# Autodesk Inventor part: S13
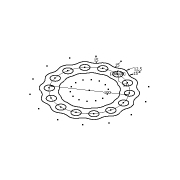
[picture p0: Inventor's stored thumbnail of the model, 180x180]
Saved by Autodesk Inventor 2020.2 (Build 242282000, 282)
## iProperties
Created: 2016-06
Part Number: S13
Material: Ogólny
Document SubType Name: Modeling
Designer: F.Stasiak
Density: 1 g/cm^3
Appearance: Domyślna
Manager: www.cadconsulting.pl
Company: Fabian Stasiak CAD Consulting
Author: F.Stasiak
Subject: Zbiór ćwiczeń. Autodesk Inventor 2020. Kurs podstawowy
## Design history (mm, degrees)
sketch "Szkic1"
  geometry: C1 r 6.5 at (0, 50); C2 r 6.5 at (-21.694, 45.048); C3 r 6.5 at (-39.092, 31.174); C4 r 6.5 at (-48.746, 11.126); C5 r 6.5 at (-48.746, -11.126); C6 r 6.5 at (-39.092, -31.174); C7 r 6.5 at (-21.694, -45.048); C8 r 6.5 at (0, -50); C9 r 6.5 at (21.694, -45.048); C10 r 6.5 at (39.092, -31.174); C11 r 6.5 at (48.746, -11.126); C12 r 6.5 at (48.746, 11.126); C13 r 6.5 at (39.092, 31.174); C14 r 6.5 at (21.694, 45.048); A1 r 50 centre (0, 0) between (0, 50) and (-39.092, -31.174); A2 r 12.5 centre (0, 50) between (7.474, 60.019) and (-7.474, 60.019); A3 r 12.5 centre (0, 50) between (-2.387, 37.73) and (2.387, 37.73); A4 r 15 centre (-16.443, 72.042) between (-19.307, 57.318) and (-7.474, 60.019); A5 r 15 centre (-5.251, 23.006) between (-2.387, 37.73) and (-14.22, 35.029); A6 r 15 centre (16.443, 72.042) between (7.474, 60.019) and (19.307, 57.318); A7 r 15 centre (5.251, 23.006) between (14.22, 35.029) and (2.387, 37.73); A8 r 12.5 centre (-21.694, 45.048) between (-19.307, 57.318) and (-32.775, 50.833); A9 r 12.5 centre (-21.694, 45.048) between (-18.521, 32.958) and (-14.22, 35.029); A10 r 12.5 centre (-39.092, 31.174) between (-42.265, 43.265) and (-51.585, 31.578); A11 r 12.5 centre (-39.092, 31.174) between (-30.987, 21.658) and (-28.01, 25.39); A12 r 12.5 centre (-48.746, 11.126) between (-56.851, 20.642) and (-60.178, 6.069); A13 r 12.5 centre (-48.746, 11.126) between (-37.315, 6.069) and (-36.253, 10.723); A14 r 12.5 centre (-48.746, -11.126) between (-60.178, -6.069) and (-56.851, -20.642); A15 r 12.5 centre (-48.746, -11.126) between (-36.253, -10.723) and (-37.315, -6.069); A16 r 12.5 centre (-39.092, -31.174) between (-51.585, -31.578) and (-42.265, -43.265); A17 r 12.5 centre (-39.092, -31.174) between (-28.01, -25.39) and (-30.987, -21.658); A18 r 12.5 centre (-21.694, -45.048) between (-32.775, -50.833) and (-19.307, -57.318); A19 r 12.5 centre (-21.694, -45.048) between (-14.22, -35.029) and (-18.521, -32.958); A20 r 12.5 centre (0, -50) between (-7.474, -60.019) and (7.474, -60.019); A21 r 12.5 centre (0, -50) between (2.387, -37.73) and (-2.387, -37.73); A22 r 12.5 centre (21.694, -45.048) between (19.307, -57.318) and (32.775, -50.833); A23 r 12.5 centre (21.694, -45.048) between (18.521, -32.958) and (14.22, -35.029); A24 r 12.5 centre (39.092, -31.174) between (42.265, -43.265) and (51.585, -31.578); A25 r 12.5 centre (39.092, -31.174) between (30.987, -21.658) and (28.01, -25.39); A26 r 12.5 centre (48.746, -11.126) between (56.851, -20.642) and (60.178, -6.069); A27 r 12.5 centre (48.746, -11.126) between (37.315, -6.069) and (36.253, -10.723); A28 r 12.5 centre (48.746, 11.126) between (60.178, 6.069) and (56.851, 20.642); A29 r 12.5 centre (48.746, 11.126) between (36.253, 10.723) and (37.315, 6.069); A30 r 12.5 centre (21.694, 45.048) between (14.22, 35.029) and (18.521, 32.958); A31 r 12.5 centre (21.694, 45.048) between (32.775, 50.833) and (19.307, 57.318); A32 r 12.5 centre (39.092, 31.174) between (51.585, 31.578) and (42.265, 43.265); A33 r 12.5 centre (39.092, 31.174) between (28.01, 25.39) and (30.987, 21.658); A34 r 15 centre (-46.073, 57.774) between (-42.265, 43.265) and (-32.775, 50.833); A35 r 15 centre (-66.577, 32.062) between (-56.851, 20.642) and (-51.585, 31.578); A36 r 15 centre (-73.895, 0) between (-60.178, -6.069) and (-60.178, 6.069); A37 r 15 centre (-66.577, -32.062) between (-51.585, -31.578) and (-56.851, -20.642); A38 r 15 centre (-46.073, -57.774) between (-32.775, -50.833) and (-42.265, -43.265); A39 r 15 centre (-16.443, -72.042) between (-7.474, -60.019) and (-19.307, -57.318); A40 r 15 centre (16.443, -72.042) between (19.307, -57.318) and (7.474, -60.019); A41 r 15 centre (46.073, -57.774) between (42.265, -43.265) and (32.775, -50.833); A42 r 15 centre (66.577, -32.062) between (56.851, -20.642) and (51.585, -31.578); A43 r 15 centre (73.895, 0) between (60.178, 6.069) and (60.178, -6.069); A44 r 15 centre (66.577, 32.062) between (51.585, 31.578) and (56.851, 20.642); A45 r 15 centre (46.073, 57.774) between (32.775, 50.833) and (42.265, 43.265); A46 r 15 centre (-14.713, 18.449) between (-18.521, 32.958) and (-28.01, 25.39); A47 r 15 centre (-21.261, 10.239) between (-30.987, 21.658) and (-36.253, 10.723); A48 r 15 centre (-23.598, 0) between (-37.315, 6.069) and (-37.315, -6.069); A49 r 15 centre (-21.261, -10.239) between (-36.253, -10.723) and (-30.987, -21.658); A50 r 15 centre (-14.713, -18.449) between (-28.01, -25.39) and (-18.521, -32.958); A51 r 15 centre (-5.251, -23.006) between (-14.22, -35.029) and (-2.387, -37.73); A52 r 15 centre (5.251, -23.006) between (2.387, -37.73) and (14.22, -35.029); A53 r 15 centre (14.713, -18.449) between (18.521, -32.958) and (28.01, -25.39); A54 r 15 centre (21.261, -10.239) between (30.987, -21.658) and (36.253, -10.723); A55 r 15 centre (23.598, 0) between (37.315, -6.069) and (37.315, 6.069); A56 r 15 centre (21.261, 10.239) between (36.253, 10.723) and (30.987, 21.658); A57 r 15 centre (14.713, 18.449) between (28.01, 25.39) and (18.521, 32.958); 1 further point
  constraints: 114 point on circle, 71 centre point, 56 tangent, 52 equal radius, 14 coincident, 1 concentric, 1 vertical alignment, 29 other
  dimensions: "d2" = 100 diameter of A1; "d3" = 13 diameter of C1; "d6" = 360 deg dimension on point (0, 0) C1.centre (derived); "d9" = 12.5 radius of A2; "d10" = 15 radius of A4 (derived); "d11" = 15 radius of A6 (derived); "d12" = 15 radius of A34 (derived)
other parameters: "d8" = 25
